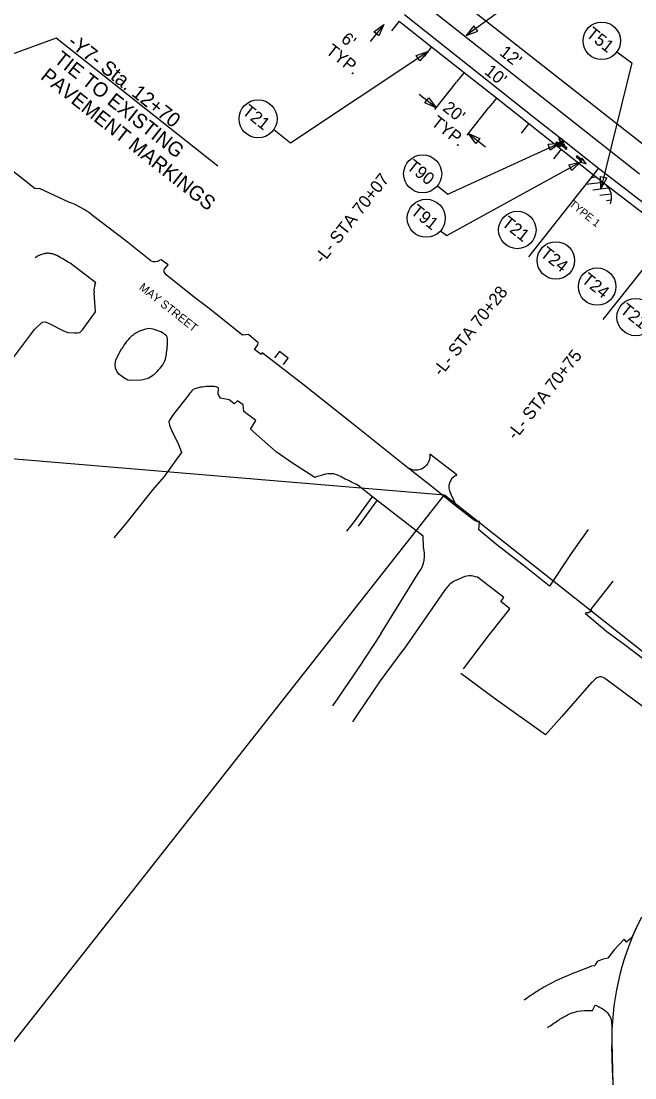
# Model space of a CAD drawing. Extents: x 553958 to 562499, y 493978 to 516388.
# Drawn here: x 557920 to 558217, y 506237 to 506749 of the extents above; entities that cross this region are included whole.
import ezdxf

# ---------------------------------------------------------------- set-up
doc = ezdxf.new("R2010")
doc.units = 0
for name, color, linetype in [('Default', 7, 'Continuous'), ('Prop Approach Slab', 7, 'Continuous'), ('Prop Conc 4in Sidewalk', 7, 'Continuous'), ('Prop EOT', 7, 'Continuous'), ('Prop Erosion Rip Rap Class II Label', 7, 'Continuous'), ('Prop Horizontal Alignment Tick Small', 7, 'Continuous'), ('Prop SS Fill Line', 7, 'Continuous'), ('Prop Superelevation Label', 7, 'Continuous'), ('Raster_Level_0', 7, 'Continuous'), ('Scratch_Level_0', 7, 'Continuous'), ('Scratch_Level_3', 7, 'Continuous'), ('Scratch_Level_4', 7, 'Continuous'), ('Sheet Plan CELL', 7, 'Continuous'), ('Sheet Plot Border Inside CELL', 7, 'Continuous')]:
    doc.layers.add(name, color=color, linetype=linetype)

msp = doc.modelspace()

# ---------------------------------------------------------------- linework, layer by layer
at = {"layer": 'Default'}
msp.add_lwpolyline([(558133.86, 506435.33), (558146.43, 506452.05), (558153.47, 506460.7)], dxfattribs=at)
at = {"layer": 'Prop Approach Slab'}
for p, q in [((558199.3, 506677.87), (558165.34, 506634.92)), ((558236.58, 506649.04), (558201.37, 506604.52))]:
    msp.add_line(p, q, dxfattribs=at)
msp.add_lwpolyline([(558014.97, 506678.87), (557936.61, 506740.83), (557856.04, 506711.44)], dxfattribs=at)
at = {"layer": 'Prop EOT'}
for p, q in [((558199.3, 506677.87), (558236.58, 506649.04)), ((558202.77, 506670.03), (558234.28, 506645.76))]:
    msp.add_line(p, q, dxfattribs=at)
at = {"layer": 'Prop Erosion Rip Rap Class II Label'}
for points in [[(557425.46, 506933.59), (557889.73, 506539.36), (558124.72, 506519.69), (558557.87, 506177.2), (558959.56, 506684.21), (558454.57, 507154), (558185.43, 507366.81), (557535.46, 507286.55), (557335.3, 506986.11)], [(558124.72, 506519.69), (558557.87, 506177.2), (558410.26, 505507.28), (557974.76, 505851.63), (557743.04, 506034.85)]]:
    msp.add_lwpolyline(points, close=True, dxfattribs=at)
at = {"layer": 'Prop Horizontal Alignment Tick Small'}
for p, q in [((558179.39, 506688.94), (558179.54, 506689.14)), ((558179.39, 506688.94), (558179.54, 506689.14)), ((558180.03, 506689.78), (558180.18, 506689.98)), ((558180.03, 506689.78), (558180.18, 506689.98)), ((558180.29, 506690.53), (558180.48, 506690.68)), ((558181.44, 506688.75), (558180.29, 506690.53)), ((558180.49, 506690.66), (558181.58, 506688.98)), ((558180.88, 506690.88), (558181.03, 506691.07)), ((558180.88, 506690.88), (558181.03, 506691.07)), ((558181.19, 506690.02), (558181.29, 506690.23)), ((558181.78, 506689.74), (558181.19, 506690.02)), ((558181.29, 506690.23), (558182.05, 506689.87)), ((558182.82, 506687.81), (558181.44, 506688.75)), ((558181.53, 506691.72), (558181.68, 506691.91)), ((558181.53, 506691.72), (558181.68, 506691.91)), ((558181.58, 506688.98), (558181.78, 506689.74)), ((558182.05, 506689.87), (558181.79, 506688.89)), ((558181.79, 506688.89), (558182.69, 506688.27)), ((558182.45, 506689.63), (558182.69, 506689.44)), ((558182.69, 506688.27), (558182.45, 506689.63)), ((558182.69, 506689.44), (558182.94, 506688.12)), ((558182.94, 506688.12), (558182.82, 506687.81)), ((558183.75, 506688.15), (558183.66, 506688.03)), ((558183.75, 506688.15), (558183.66, 506688.03)), ((558183.16, 506687.38), (558183.07, 506687.26)), ((558183.16, 506687.38), (558183.07, 506687.26))]:
    msp.add_line(p, q, dxfattribs=at)
msp.add_lwpolyline([(558191.42, 506682.72), (558191.49, 506681.78), (558188.82, 506683.88), (558188.43, 506683.38), (558191.1, 506681.28), (558190.17, 506681.13), (558193.34, 506679.92)], close=True, dxfattribs=at)
msp.add_lwpolyline([(558191.42, 506682.72), (558191.49, 506681.78), (558188.82, 506683.88), (558188.43, 506683.38), (558191.1, 506681.28), (558190.17, 506681.13), (558193.34, 506679.92)], close=True, dxfattribs=at)
for radius, start, end in [(0.41, 52.2816, 232.2816), (0.563, 232.2816, 52.2816), (0.563, 232.2816, 52.2816)]:
    msp.add_arc((558183.41, 506687.7), radius, start, end, dxfattribs=at)
for centre, major_axis, ratio, start_param, end_param in [((558179.79, 506689.46), (-1.18, 0.91), 0.435841, 4.712389, 7.853982), ((558179.79, 506689.46), (-0.99, 0.765), 0.325967, 4.712389, 7.853982), ((558179.79, 506689.46), (-1.18, 0.91), 0.435841, 1.570796, 4.712389), ((558179.79, 506689.46), (-0.99, 0.765), 0.325967, 1.570796, 4.712389), ((558181.28, 506691.39), (-1.18, 0.91), 0.435841, 4.712389, 7.853982), ((558181.28, 506691.39), (-0.99, 0.765), 0.325967, 4.712389, 7.853982), ((558181.28, 506691.39), (-1.18, 0.91), 0.435841, 1.570796, 4.712389), ((558181.28, 506691.39), (-0.99, 0.765), 0.325967, 1.570796, 4.712389)]:
    msp.add_ellipse(centre, major_axis=major_axis, ratio=ratio, start_param=start_param, end_param=end_param, dxfattribs=at)
at = {"layer": 'Prop SS Fill Line'}
msp.add_line((558205.96, 506241.14), (558205.7, 506252.95), dxfattribs=at)
msp.add_lwpolyline([(558212.1, 506124.49), (558211.07, 506146.1), (558205.96, 506241.14)], dxfattribs=at)
msp.add_arc((558334.66, 506255.85), 129, 153.8089, 181.2908, dxfattribs=at)
at = {"layer": 'Raster_Level_0'}
msp.add_line((557928.68, 506904.52), (558219.1, 506675.14), dxfattribs=at)
at = {"layer": 'Scratch_Level_0'}
for p, q in [((557955.8, 506622.31), (557943.4, 506631.81)), ((557955.53, 506621.84), (557955.8, 506622.31)), ((558000.76, 506567.95), (557998.31, 506564.94)), ((558093.86, 506452.33), (558112.47, 506482.37)), ((558124.65, 506473.31), (558104.66, 506444.4)), ((558195.96, 506428.88), (558192.43, 506424.94)), ((558221.51, 506416.52), (558202.8, 506430.39)), ((558164.86, 506276.05), (558163.24, 506274.9)), ((558174.57, 506261.56), (558175.04, 506261.95)), ((558205.63, 506262.59), (558205.68, 506260.73)), ((558205.68, 506260.73), (558205.67, 506259.63))]:
    msp.add_line(p, q, dxfattribs=at)
for points in [[(557942.77, 506661.5), (557928.53, 506667.97), (557926.47, 506667.94), (557896.75, 506691.22), (557868.37, 506711.35), (557860.8, 506717.49)], [(557982.44, 506633.08), (557970.32, 506642.69), (557954.18, 506655.01)], [(557988.92, 506628.75), (557990.8, 506631.06), (557987.43, 506633.55), (557986.88, 506633.39)], [(558138.57, 506507.73), (558130.7, 506513.87), (558118.06, 506524.02), (558105.52, 506533.94), (558080.48, 506553.87), (558056.19, 506573.16), (558045.6, 506581.4), (558041.25, 506584.67), (558036.42, 506588.47), (558035.91, 506587.71), (558032.62, 506590.05), (558034.28, 506592.29), (558034.43, 506593.33), (558029.75, 506597.27), (558026.91, 506596.98), (558010.02, 506610.4), (558004.32, 506614.8), (557989.98, 506626.29), (557988.93, 506627.61)], [(557949.43, 506599.64), (557955.64, 506608.38), (557955.03, 506617.54)], [(558063.03, 506528.5), (558061.88, 506528.15), (558051.06, 506535.04), (558043.11, 506540.5), (558030.69, 506551.47), (558033.3, 506555.69), (558027.59, 506560.07), (558027.17, 506563.22), (558024.4, 506565.13), (558022.88, 506563.74), (558020.35, 506565.77), (558016.27, 506566.51), (558015.02, 506568.37), (558015.31, 506571.54), (558014.1, 506572.02)], [(558114.49, 506494.32), (558114.37, 506499.74), (558092.1, 506516.99), (558089.81, 506518.73), (558082.92, 506524.26)], [(558186.29, 506491.73), (558175.58, 506475.49), (558164.19, 506484.53), (558150.09, 506495.47), (558141.25, 506502.71), (558141.55, 506506.73), (558141.35, 506506.72)], [(558153.47, 506460.7), (558156.26, 506464.43), (558151.96, 506468), (558153.49, 506469.88), (558140.68, 506479.75)], [(558259.33, 506410.84), (558252.55, 506415.91), (558245.48, 506421.08), (558240.32, 506425.14), (558236.14, 506427.97), (558234.14, 506428.47), (558232.29, 506430), (558232.12, 506431.57), (558212.27, 506446.74), (558203.26, 506453.38), (558193, 506461.97), (558193.44, 506462.7), (558194.35, 506462.73), (558196.07, 506463.73), (558195.67, 506464.37), (558197.03, 506465.92), (558206.28, 506477.79)], [(558093.86, 506452.33), (558082.97, 506435.85), (558073, 506421.17), (558070.42, 506417.41)], [(558080.3, 506409.81), (558082.54, 506413.19), (558093.64, 506429.64), (558104.66, 506444.4)], [(558220.05, 506315.07), (558217.3, 506309.46), (558215.39, 506305.29), (558212.88, 506303.02), (558211.62, 506304.46), (558206.76, 506299.35), (558203.8, 506295.34), (558201.04, 506294.56), (558198.63, 506293.71), (558197.82, 506292.42), (558197.48, 506291.59), (558195.91, 506291.34)], [(558195.77, 506269.9), (558196.38, 506269.9), (558197.62, 506272.47), (558198.22, 506272.33)]]:
    msp.add_lwpolyline(points, dxfattribs=at)
for centre, major_axis, ratio, start_param, end_param in [((557929.67, 506625.88), (-38.24, 3.4), 0.987625, 4.107523, 4.451833), ((557984.41, 506637.43), (4.67, 1.25), 0.977465, 4.036915, 4.993756), ((557989.38, 506628.18), (0.742, -0.11), 0.961066, 2.387999, 4.204285), ((557963.65, 506618.72), (-8.7, 0.4), 0.994255, 5.961631, 6.467018), ((558141.64, 506511.86), (-1.37, -4.96), 0.998246, 5.911094, 6.496023), ((558101.55, 506490.36), (8.54, 10.49), 0.999887, 4.763805, 5.692516), ((559065.24, 506257.8), (-640.46, 579.19), 0.989906, 0.738123, 0.80145)]:
    msp.add_ellipse(centre, major_axis=major_axis, ratio=ratio, start_param=start_param, end_param=end_param, dxfattribs=at)
for points in [[(557943.4, 506631.81), (557937.26, 506635.4), (557936.89, 506635.6), (557936.51, 506635.79), (557935.72, 506636.11), (557934.03, 506636.54), (557932.32, 506636.66), (557931.48, 506636.59), (557931.08, 506636.52), (557930.68, 506636.43), (557929.59, 506636.09), (557928.51, 506635.64), (557927.46, 506635.09), (557926.47, 506634.45)], [(557983.87, 506577.81), (557989.27, 506584.59), (557990.42, 506591.12), (557990.58, 506592.81), (557990.54, 506594.67), (557990.53, 506595.26), (557985.6, 506599.31), (557981.78, 506600.18), (557977.9, 506599.29), (557973.34, 506596.62), (557970.76, 506593.89), (557968.26, 506590.39)], [(558014.1, 506572.02), (558010.39, 506572.18), (558006.51, 506571.75), (558003.05, 506570.65), (558000.76, 506567.95)], [(558082.92, 506524.26), (558075.76, 506527.79), (558070.22, 506529.9), (558066.04, 506529.39), (558063.03, 506528.5)], [(558140.68, 506479.75), (558136.47, 506480.43), (558132.74, 506479.38), (558128.33, 506477.2), (558124.65, 506473.31)], [(558202.8, 506430.39), (558201.01, 506431.41), (558198.86, 506431.2), (558197.26, 506430.09), (558195.96, 506428.88)], [(558195.91, 506291.34), (558191.44, 506289.67), (558180.05, 506284.89), (558171.74, 506280.61), (558164.86, 506276.05)], [(558175.04, 506261.95), (558180.17, 506265.47), (558184.93, 506268.11), (558189.32, 506269.61), (558195.77, 506269.9)], [(558198.22, 506272.33), (558200.72, 506271.07), (558203.39, 506268.95), (558205.16, 506266), (558205.63, 506262.59)]]:
    msp.add_spline(points, degree=3, dxfattribs=at)
at = {"layer": 'Scratch_Level_3'}
for p, q in [((558130.58, 506514.08), (558127.59, 506520.54)), ((558080.61, 506506.15), (558089.64, 506518.56)), ((558091.88, 506516.92), (558082.94, 506504.49)), ((558077.46, 506502.16), (558080.61, 506506.15)), ((558194.29, 506502.84), (558186.29, 506491.73))]:
    msp.add_line(p, q, dxfattribs=at)
for points in [[(557890.78, 506555.54), (557895.53, 506561.33), (557902.56, 506569.71), (557915.55, 506585.6), (557926.16, 506599.82), (557929.83, 506603.29), (557931.3, 506603.42), (557932.88, 506602.84), (557940.18, 506599.09), (557942.3, 506598.31), (557945.54, 506598.1), (557946.96, 506598.09), (557948.1, 506598.27), (557949.42, 506599.61)], [(557983.82, 506577.71), (557981.14, 506576), (557977.95, 506575.27), (557973.29, 506575.1), (557971.31, 506575.19), (557969.39, 506576.3), (557967.07, 506578.16), (557965.96, 506579.51), (557965.42, 506581.08), (557965.25, 506582.81), (557965.56, 506585.1), (557968.26, 506590.39)], [(558046.67, 506582.73), (558048.98, 506585.84), (558044.81, 506589.08), (558042.36, 506586.01)], [(557998.31, 506564.94), (557993.45, 506558.69), (557991.59, 506555.84), (557991.25, 506554.96), (557991.46, 506553.5), (557992.97, 506549.84), (557995.65, 506544.48), (557997.34, 506540.22), (557993.74, 506535.28), (557988.89, 506528.57), (557983.53, 506522.28), (557977.99, 506515.36), (557970.31, 506505.83), (557964.57, 506498.8)], [(558130.24, 506529.02), (558130.64, 506529.32), (558117.63, 506539.43)], [(558192.43, 506424.94), (558181.46, 506412.38), (558173.63, 506403.4), (558149.39, 506420.76), (558132.62, 506433.15)]]:
    msp.add_lwpolyline(points, dxfattribs=at)
msp.add_ellipse((558132.76, 506523.57), major_axis=(4.58, -3.88), ratio=0.999134, start_param=2.705656, end_param=4.375214, dxfattribs=at)
msp.add_spline([(558117.63, 506539.43), (558117.64, 506538.98), (558116.44, 506534.66), (558113.56, 506532.17), (558111, 506531.63), (558108.65, 506531.99), (558107.72, 506532.4)], degree=3, dxfattribs=at)
at = {"layer": 'Scratch_Level_4'}
for p, q in [((558102.76, 506749.1), (558099.06, 506744.43)), ((558118.45, 506736.7), (558114.76, 506732.03)), ((558134.14, 506724.29), (558130.45, 506719.63)), ((558149.86, 506711.86), (558146.18, 506707.2)), ((558165.48, 506699.51), (558161.8, 506694.86)), ((558181.13, 506687.14), (558177.46, 506682.49))]:
    msp.add_line(p, q, dxfattribs=at)
at = {"layer": 'Sheet Plan CELL'}
for p, q in [((558095.24, 506747.43), (558088.75, 506739.23)), ((558120, 506706.34), (558130.48, 506719.6)), ((558120.65, 506707.16), (558112.44, 506713.65)), ((558135.69, 506693.93), (558146.18, 506707.2)), ((558136.31, 506694.72), (558144.51, 506688.23))]:
    msp.add_line(p, q, dxfattribs=at)
for points in [[(558253.07, 506822.27), (558249.56, 506824.95), (558135.14, 506742.09)], [(558042.02, 506696.55), (558050.15, 506690.13), (558116.6, 506734.36)], [(558208.14, 506734.21), (558215.37, 506728.94), (558200.33, 506667.92)], [(558121.33, 506669.41), (558126.35, 506665.26), (558179.2, 506689.55)], [(558122.77, 506647.55), (558125.85, 506645.34), (558190.72, 506680.92)]]:
    msp.add_lwpolyline(points, dxfattribs=at)
for points in [[(558090.43, 506743.85), (558095.24, 506747.43), (558092.86, 506741.92)], [(558138.93, 506746.75), (558135.14, 506742.09), (558140.75, 506744.23)], [(558110.93, 506732.42), (558116.6, 506734.36), (558112.66, 506729.84)], [(558117.07, 506711.97), (558120.65, 506707.16), (558115.14, 506709.54)], [(558139.89, 506689.91), (558136.31, 506694.72), (558141.82, 506692.34)], [(558174.84, 506689.51), (558180.82, 506690.01), (558175.89, 506686.59)], [(558184.89, 506679.5), (558190.72, 506680.92), (558186.39, 506676.77)], [(558203.22, 506673.17), (558200.33, 506667.92), (558200.21, 506673.91)]]:
    msp.add_lwpolyline(points, close=True, dxfattribs=at)
for centre, radius in [((558200.83, 506739.56), 9.06), ((558034.43, 506701.78), 9.22), ((558114.11, 506675.14), 9.22), ((558115.84, 506653.64), 9.22), ((558159.93, 506647.96), 9.06), ((558178.61, 506633.19), 9.06), ((558198.58, 506620.53), 9.06), ((558217.24, 506605.78), 9.06)]:
    msp.add_circle(centre, radius, dxfattribs=at)
at = {"layer": 'Sheet Plot Border Inside CELL'}
for p, q in [((558073.12, 506805.73), (558233.17, 506679.7)), ((558102.76, 506749.1), (558118.45, 506736.7)), ((558105.24, 506752.24), (558120.93, 506739.84)), ((558120.93, 506739.84), (558136.62, 506727.43)), ((558118.45, 506736.7), (558134.14, 506724.3)), ((558134.14, 506724.3), (558149.83, 506711.89)), ((558136.62, 506727.43), (558152.31, 506715.03)), ((558152.31, 506715.03), (558168, 506702.63)), ((558149.83, 506711.89), (558165.52, 506699.49)), ((558165.48, 506699.52), (558181.17, 506687.11)), ((558167.96, 506702.65), (558183.65, 506690.25)), ((558183.61, 506690.28), (558199.3, 506677.87)), ((558181.13, 506687.14), (558196.82, 506674.74)), ((558196.82, 506674.74), (558193.15, 506670.1)), ((558195.79, 506673.43), (558198.13, 506673.7)), ((558196.82, 506674.74), (558202.77, 506670.03)), ((558193.15, 506670.1), (558201.46, 506671.07)), ((558196.48, 506667.47), (558204.17, 506668.36)), ((558199.82, 506664.84), (558205.35, 506665.48)), ((558203.15, 506662.21), (558205.46, 506662.48))]:
    msp.add_line(p, q, dxfattribs=at)
msp.add_arc((558196.83, 506663.63), 8.73, 340.3703, 47.1356, dxfattribs=at)

# ---------------------------------------------------------------- texts
at = {"layer": 'Prop Approach Slab'}
for s, p in [('-Y7- Sta. 12+70', (557941.66, 506737.93)), ('TIE TO EXISTING', (557935.15, 506729.7)), ('PAVEMENT MARKINGS', (557928.64, 506721.46))]:
    msp.add_text(s, height=7, rotation=321.6667, dxfattribs=at).set_placement(p)
at = {"layer": 'Prop Conc 4in Sidewalk'}
msp.add_text('TYPE 1', height=3.75, rotation=321.3322, dxfattribs=at).set_placement((558184.74, 506659.92))
at = {"layer": 'Prop Superelevation Label'}
msp.add_text('MAY STREET', height=4, rotation=321.6667, dxfattribs=at).set_placement((557976.45, 506619.51))
at = {"layer": 'Sheet Plan CELL'}
for s, rotation, p in [('T51', 321.6667, (558192.85, 506742.04)), (" 6'", 321.6667, (558072.38, 506740.92)), ('TYP.', 321.6667, (558066.8, 506733.86)), ("12'", 321.6667, (558150.87, 506733.11)), ("10'", 321.6667, (558143.61, 506723.93)), ('T21', 321.6667, (558026.29, 506704.54)), ("20'", 321.6667, (558123.36, 506706.17)), ('TYP.', 321.6667, (558117.78, 506699.11)), ('T90', 321.6667, (558105.97, 506677.9)), ('-L- STA 70+07', 51.6698, (558065.79, 506631.26)), ('T91', 321.6667, (558107.84, 506656.14)), ('T21', 321.6667, (558151.95, 506650.44)), ('T24', 321.6667, (558170.63, 506635.67)), ('T24', 321.6667, (558190.61, 506623.01)), ('-L- STA 70+28', 51.6698, (558123.15, 506576.71)), ('T21', 321.6667, (558209.27, 506608.26)), ('-L- STA 70+75', 51.6698, (558159.09, 506545.91))]:
    msp.add_text(s, height=6, rotation=rotation, dxfattribs=at).set_placement(p)

doc.saveas('drawing.dxf')
